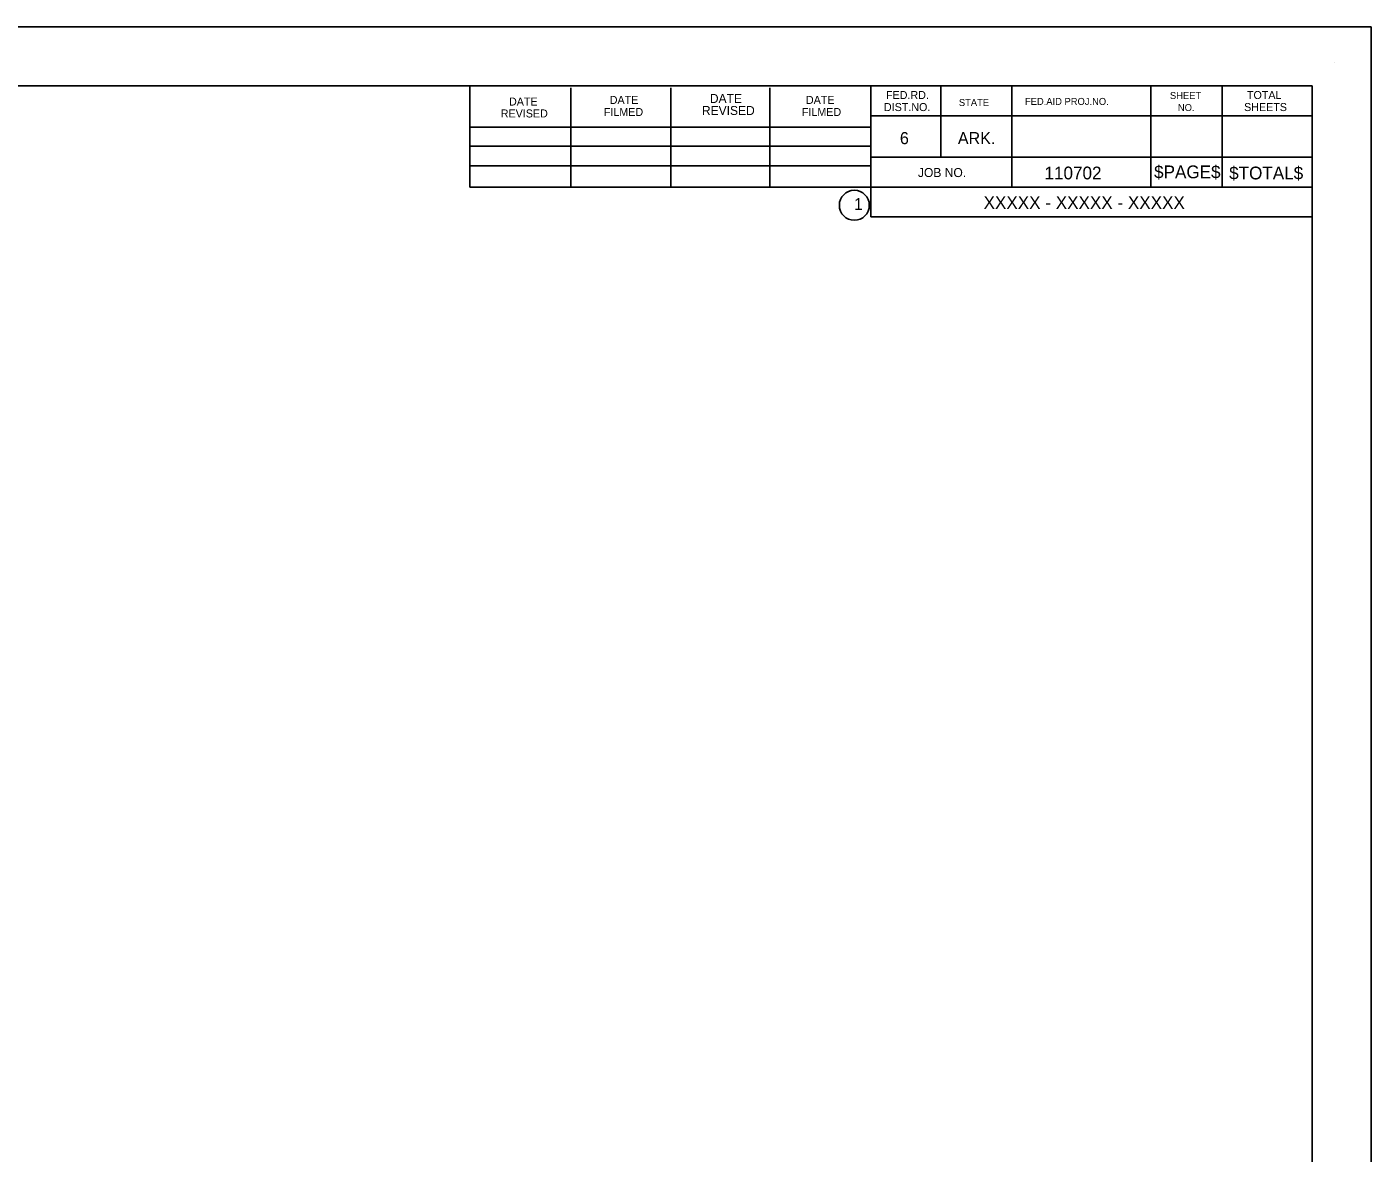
# Model space of a CAD drawing. Extents: x 16 to 1228740, y 11 to 152440.
# Drawn here: x 17.396 to 18.49, y 11.626 to 12.543 of the extents above; entities that cross this region are included whole.
import ezdxf

# ---------------------------------------------------------------- set-up
doc = ezdxf.new("R2010")
doc.units = 0
doc.layers.add('B_Copy In', color=7, linetype='Continuous')
doc.layers.add('R_Border', color=7, linetype='Continuous')

msp = doc.modelspace()

# ---------------------------------------------------------------- linework, layer by layer
at = {"layer": 'R_Border'}
for p, q in [((18.4604, 12.514), (18.4604, 12.514)), ((15.7833, 12.4948), (18.4422, 12.4948)), ((17.7567, 12.4124), (17.7567, 12.4948)), ((17.8389, 12.4124), (17.8389, 12.4931)), ((17.9202, 12.4124), (17.9202, 12.4931)), ((18.0009, 12.4124), (18.0009, 12.4931)), ((18.083, 12.4948), (18.083, 12.3881)), ((18.14, 12.4948), (18.14, 12.4369)), ((18.1979, 12.4948), (18.1979, 12.4124)), ((18.311, 12.4948), (18.311, 12.4124)), ((18.3689, 12.4948), (18.3689, 12.4124)), ((18.4422, 10.7576), (18.4422, 12.4948)), ((18.4422, 12.4703), (18.083, 12.4703)), ((18.4422, 12.4704), (18.4422, 12.4704)), ((17.7567, 12.4613), (18.083, 12.4613)), ((17.7567, 12.4458), (18.083, 12.4458)), ((18.4422, 12.4369), (18.083, 12.4369)), ((18.1077, 12.4369), (18.4422, 12.4369)), ((17.7567, 12.4124), (17.7567, 12.4296)), ((17.7567, 12.4296), (18.083, 12.4296)), ((18.4422, 12.4124), (17.7567, 12.4124)), ((18.083, 12.3881), (18.4422, 12.3881))]:
    msp.add_line(p, q, dxfattribs=at)
msp.add_lwpolyline([(15.6569, 12.5428), (18.4903, 12.5428), (18.4903, 10.7095), (15.6569, 10.7095)], close=True, dxfattribs=at)
msp.add_circle((18.0696, 12.3976), 0.0122, dxfattribs=at)

# ---------------------------------------------------------------- texts
at = {"layer": 'B_Copy In'}
msp.add_text('XXXXX - XXXXX - XXXXX', height=0.0104, dxfattribs=at).set_placement((18.1748, 12.3946))
at = {"layer": 'R_Border'}
for s, height, p in [('DATE', 0.00652, (17.7885, 12.4788)), ('DATE', 0.00652, (17.8705, 12.4801)), ('DATE', 0.00733, (17.952, 12.4809)), ('DATE', 0.00652, (18.0302, 12.4801)), ('FED.RD.', 0.00652, (18.0954, 12.4841)), ('SHEET', 0.0057, (18.3265, 12.4841)), ('TOTAL', 0.00652, (18.3892, 12.4841)), ('REVISED', 0.00652, (17.7818, 12.4691)), ('FILMED', 0.00652, (17.8657, 12.4703)), ('REVISED', 0.00733, (17.9455, 12.4711)), ('FILMED', 0.00652, (18.0269, 12.4703)), ('DIST.NO.', 0.00652, (18.0937, 12.4743)), ('STATE', 0.0057, (18.1547, 12.4784)), ('FED.AID PROJ.NO.', 0.0057, (18.2085, 12.4793)), ('NO.', 0.0057, (18.333, 12.4743)), ('SHEETS', 0.00652, (18.3869, 12.4743)), ('6', 0.00977, (18.1067, 12.4474)), ('ARK.', 0.00977, (18.1539, 12.4474)), ('$PAGE$', 0.0104, (18.3136, 12.4196)), ('JOB NO.', 0.00733, (18.1214, 12.4206)), ('110702', 0.0104, (18.2244, 12.4187)), ('$TOTAL$', 0.0104, (18.3747, 12.4187)), ('1', 0.00977, (18.0693, 12.3937))]:
    msp.add_text(s, height=height, dxfattribs=at).set_placement(p)

doc.saveas('drawing.dxf')
